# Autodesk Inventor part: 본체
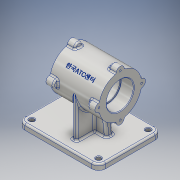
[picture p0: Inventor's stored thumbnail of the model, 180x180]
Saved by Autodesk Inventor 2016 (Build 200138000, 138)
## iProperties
Created: 2015-12
Part Number: 본체
Material: 알루미늄 6061
Document SubType Name: Modeling
Designer: Administrator
Density: 2.7 g/cm^3
Appearance: 알루미늄 - 평지
Mass: 1159.73 g
Surface Area: 814.485 cm^2
Volume: 429.528 cm^3
Author: Administrator
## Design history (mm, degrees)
sketch "스케치1"
  geometry: L1 (-70, 55)-(70, 55); L2 (70, 55)-(70, -55); L3 (70, -55)-(-70, -55); L4 (-70, -55)-(-70, 55); 3 further points
  constraints: 8 end point, 2 midpoint, 2 parallel, 1 horizontal, 1 horizontal alignment, 1 perpendicular, 1 vertical alignment
  dimensions: "d0" = 140 distance of L1.start L1.end; "d1" = 110 distance of L1.end L2.end
extrude "돌출1" new body sketch "스케치1" distance "d2" = 10; taper "d3" = 0 deg
node "작업 평면1"
sketch "스케치2"
  geometry: C1 r 37 at (-80, 55); 1 further point
  constraints: 1 centre point, 1 horizontal alignment
  dimensions: "d5" = 74 diameter of C1; "d6" = 80 distance of point (0, 55) C1.centre
extrude "돌출2" join sketch "스케치2" distance "d7" = 85; taper "d8" = 0 deg
sketch "스케치5"
  geometry: L1 (-6, -37)-(-14, -37); L2 (-14, -37)-(-14, 37); L3 (-14, 37)-(-6, 37); L4 (-6, 37)-(-6, -37); L5 (70, 55)-(70, -55) reference; L6 (70, -55)-(-70, -55) reference; 4 further points
  constraints: 8 end point, 3 midpoint, 2 parallel, 1 horizontal, 1 horizontal alignment, 1 perpendicular
  dimensions: "d14" = 8 distance of L1.start L1.end; "d15" = 80 distance from line of point (-10, -37) L5; "d17" = 74 distance of L1.end L2.end
extrude "돌출3" join sketch "스케치5" distance "d18" = 70; taper "d19" = 0 deg
sketch "스케치6"
  geometry: L1 (-32.5, 43)-(52.5, 43) reference; L2 (-70, 0)-(70, 0) reference; L3 (-70, 0)-(-70, 10) reference; L4 (70, 10)-(-70, 10) reference; L5 (70, 0)-(70, 10) reference; L6 (-10.948, 43)-(-15, 10); L7 (30.948, 43)-(35, 10); L8 (-15, 10)-(35, 10); L9 (6, 10)-(14, 10) reference; L10 (6, 10)-(6, 80) reference; L11 (6, 80)-(14, 80) reference; L12 (14, 10)-(14, 80) reference; L13 (10, 10)-(10, 20.689); L14 (-10.948, 43)-(-10.101, 49.901); L15 (-10.101, 49.901)-(30.101, 49.901); L16 (30.101, 49.901)-(30.948, 43); 1 further point
  constraints: 14 end point, 4 point on line, 1 collinear, 1 horizontal, 1 midpoint, 1 vertical
  dimensions: "d20" = 97 deg angle of L4 L6; "d21" = 97 deg angle of L4 L7; "d22" = 25 distance of L13.start L6.end; "d23" = 50 distance of L7.end L6.end; "d25" = 6.9005 distance between parallel lines of L1 L15; "d26" = 97 deg angle of L1 L16; "d48" = 97 deg angle of L14 L1
extrude "돌출4" join sketch "스케치6" stored distance "d27" = 12; taper "d28" = 0 deg
sketch "스케치11"
  geometry: L1 (-32.5, 43)-(-32.5, 43) reference; L2 (52.5, 43)-(52.5, 117) reference; L3 (-56.347, 80)-(69.729, 80); L4 (-32.5, 103.5)-(-10.8, 103.5); L5 (-10.5, 103.2)-(-10.5, 101); L6 (-10.5, 101)-(30.5, 101); L7 (30.5, 101)-(30.5, 103.2); L8 (30.8, 103.5)-(52.5, 103.5); L9 (52.5, 103.5)-(52.5, 80); L10 (52.5, 80)-(-32.5, 80); L11 (-32.5, 103.5)-(-32.5, 80); A1 r 0.3 centre (-10.8, 103.2) between (-10.5, 103.2) and (-10.8, 103.5); A2 r 0.3 centre (30.8, 103.2) between (30.8, 103.5) and (30.5, 103.2); 3 further points
  constraints: 18 end point, 8 point on line, 5 perpendicular, 4 point on circle, 4 tangent, 2 centre point, 2 horizontal, 2 midpoint, 1 equal radius, 1 horizontal alignment
  dimensions: "d38" = 47 diameter of L4 L3; "d39" = 42 diameter of L6 L3; "d40" = 41 distance between parallel lines of L7 L5; "d41" = 22 distance between parallel lines of L2 L7; "d42" = 0.3 radius of A1
revolve "회전1" sketch "스케치11" stored, may be unused: angle "d43" = 90 deg
chamfer "모따기1" distance "d44" = 1; stored, may be unused: second distance "d45" = 2, angle "d46" = 45 deg
fillet "모깎기2" dims "d49" = 4
fillet "모깎기3" dims "d50" = 3
fillet "모깎기4" dims "d51" = 12
fillet "모깎기5" dims "d52" = 3
sketch "스케치12"
  geometry: L1 (58, 55)-(-58, 55) reference; L2 (70, -43)-(70, 43) reference; L3 (17.5, 0)-(-52.5, 0) reference; L4 (70, 43)-(70, -43) reference; L5 (58, -55)-(-58, -55) reference; L6 (-70, -43)-(-70, 43) reference; L7 (-58, 55)-(58, 55) reference; C1 r 4 at (-58, 43); C2 r 4 at (-58, -43); C3 r 4 at (58, 43); C4 r 4 at (58, -43); A1 r 12 centre (58, 43) between (70, 43) and (58, 55) reference; A2 r 12 centre (58, -43) between (58, -55) and (70, -43) reference; A3 r 12 centre (-58, -43) between (-70, -43) and (-58, -55) reference; A4 r 12 centre (-58, 43) between (-58, 55) and (-70, 43) reference; 1 further point
  constraints: 4 centre point, 2 vertical alignment, 1 horizontal alignment
  dimensions: "d53" = 8 diameter of C1; "d54" = 8 diameter of C2; "d55" = 8 diameter of C3; "d56" = 8 diameter of C4; "d58" = 12 distance from line of C3.centre L1; "d59" = 43 vertical distance of point (0, 0) C1.centre; "d60" = 86 distance of C2.centre C1.centre; "d61" = 12 distance from line of L6 C1.centre; "d62" = 116 distance of C3.centre C1.centre
extrude "돌출6" cut sketch "스케치12" stored distance "d63" = 15; taper "d64" = 0 deg
chamfer "모따기2" distance "d65" = 1; stored, may be unused: second distance "d66" = 2, angle "d67" = 45 deg
node "작업 평면6"
  node "작업 평면4"
  node "작업 평면5"
sketch "스케치18" dims "d65" = 1
  geometry: L1 (0, 37)-(85, 37) reference; L2 (96.815, 37)-(59.527, 37); L3 (85, 37)-(85, 44); L4 (85, 44)-(72.548, 44); L5 (72.548, 44)-(70, 37); L6 (85, -37)-(85, 37) reference; L7 (70, 37)-(85, 37); 1 further point
  constraints: 10 end point, 3 point on line, 1 horizontal, 1 perpendicular, 1 vertical
  dimensions: "d88" = 110 deg angle of L1 L5; "d89" = 14 diameter of L4 L2; "d90" = 15 distance of L1.end L5.end
revolve "회전2" sketch "스케치18" stored, may be unused: angle "d91" = 90 deg
sketch "스케치19"
  geometry: L1 (84, 23.5)-(84, -23.5) reference; L2 (84, 0)-(109.74, 0); 1 further point
  constraints: 2 end point, 1 horizontal, 1 midpoint
node "작업 평면7"
sketch "스케치20"
  geometry: C1 r 24.5 at (80, 55) reference; A1 r 37 centre (80, 55) between (73.031, 91.338) and (43.662, 61.969) reference; A2 r 7 centre (43, 55) between (43.662, 61.969) and (43.662, 48.031) reference; A3 r 37 centre (80, 55) between (43.662, 48.031) and (73.031, 18.662) reference; A4 r 7 centre (80, 18) between (73.031, 18.662) and (86.969, 18.662) reference; A5 r 37 centre (80, 55) between (86.969, 18.662) and (116.338, 48.031) reference; A6 r 7 centre (117, 55) between (116.338, 48.031) and (116.338, 61.969) reference; A7 r 37 centre (80, 55) between (116.338, 61.969) and (86.969, 91.338) reference; A8 r 7 centre (80, 92) between (86.969, 91.338) and (73.031, 91.338) reference; 5 further points
  constraints: 4 coincident
hole "구멍2" sketch "스케치20" at (117, 55), (80, 92), (80, 18), (43, 55) diameter "d95" = 3.242; stored, may be unused: countersink angle "d99" = 90 deg, drill point angle "d101" = 118 deg; dims "d96" = 9, "d97" = 4, "d98" = 2, "d100" = 11
fillet "모깎기8" dims "d102" = 3
fillet "모깎기9" dims "d103" = 3
sketch "스케치21"
  geometry: L1 (0, 0)-(0, 70.031); L2 (0, 0)-(-38.77, 38.77); C1 r 1.621 at (0, -37) reference; C2 r 1.621 at (-37, 0) reference; C3 r 1.621 at (0, 37) reference; C4 r 1.621 at (37, 0) reference; C5 r 24.5 at (0, 0) reference; A1 r 3 centre (-38.77, 9.842) between (-38.239, 6.889) and (-35.862, 9.104) reference; A2 r 7 centre (-37, 0) between (-38.239, 6.889) and (-38.239, -6.889) reference; A3 r 3 centre (-38.77, -9.842) between (-35.862, -9.104) and (-38.239, -6.889) reference; A4 r 37 centre (0, 0) between (-35.862, -9.104) and (-9.104, -35.863) reference; A5 r 3 centre (-9.842, -38.77) between (-6.889, -38.239) and (-9.104, -35.863) reference; A6 r 7 centre (0, -37) between (-6.889, -38.239) and (6.889, -38.239) reference; A7 r 3 centre (9.842, -38.77) between (9.104, -35.863) and (6.889, -38.239) reference; A8 r 37 centre (0, 0) between (9.104, -35.863) and (35.863, -9.104) reference; A9 r 3 centre (38.77, -9.842) between (38.239, -6.889) and (35.863, -9.104) reference; A10 r 7 centre (37, 0) between (38.239, -6.889) and (38.239, 6.889) reference; A11 r 3 centre (38.77, 9.842) between (35.863, 9.104) and (38.239, 6.889) reference; A12 r 37 centre (0, 0) between (35.863, 9.104) and (9.104, 35.863) reference; A13 r 3 centre (9.842, 38.77) between (6.889, 38.239) and (9.104, 35.863) reference; A14 r 7 centre (0, 37) between (6.889, 38.239) and (-6.889, 38.239) reference; A15 r 3 centre (-9.842, 38.77) between (-9.104, 35.863) and (-6.889, 38.239) reference; A16 r 37 centre (0, 0) between (-9.104, 35.863) and (-35.862, 9.104) reference; A17 r 37 centre (0, 0) between (-9.104, 35.863) and (-35.862, 9.104) reference; 2 further points
  constraints: 4 end point, 1 point on circle, 1 point on line, 1 vertical
  dimensions: "d104" = 45 deg angle of L1 L2
  node "투영된 루프10"
node "작업 평면8"
sketch "스케치22"
  geometry: L1 (-42.5, 37)-(42.5, 37) reference; L2 (-42.5, -18.921)-(-42.5, 18.921) reference; 4 further points
  constraints: 2 midpoint, 1 horizontal alignment, 1 vertical alignment, 1 other
feature "엠보싱2" sketch "스케치22" dims "d0" = 140, "d1" = 110, "d15" = 80, "d105" = 0.5, "d106" = 0
node "솔리드1"
pattern_circular "원형 패턴1" dims angle "d93" = 360 deg
mirror "대칭3"
mirror "대칭4"
node "투영된 루프2"
node "투영된 루프3"
node "투영된 루프6"
node "투영된 루프9"
other parameters: "d4" = -37.5
